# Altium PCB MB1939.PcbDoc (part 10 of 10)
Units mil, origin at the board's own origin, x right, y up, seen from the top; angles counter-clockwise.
Board outline 5910.64 x 4335.93 mil, 6 copper layers (Top Layer, l2_GND, L3_SIG, L4_VCC, L5_GND, Bottom Layer), stack 58.424 mil thick; 635 components, 489 nets, 2289 pads, 1388 vias.
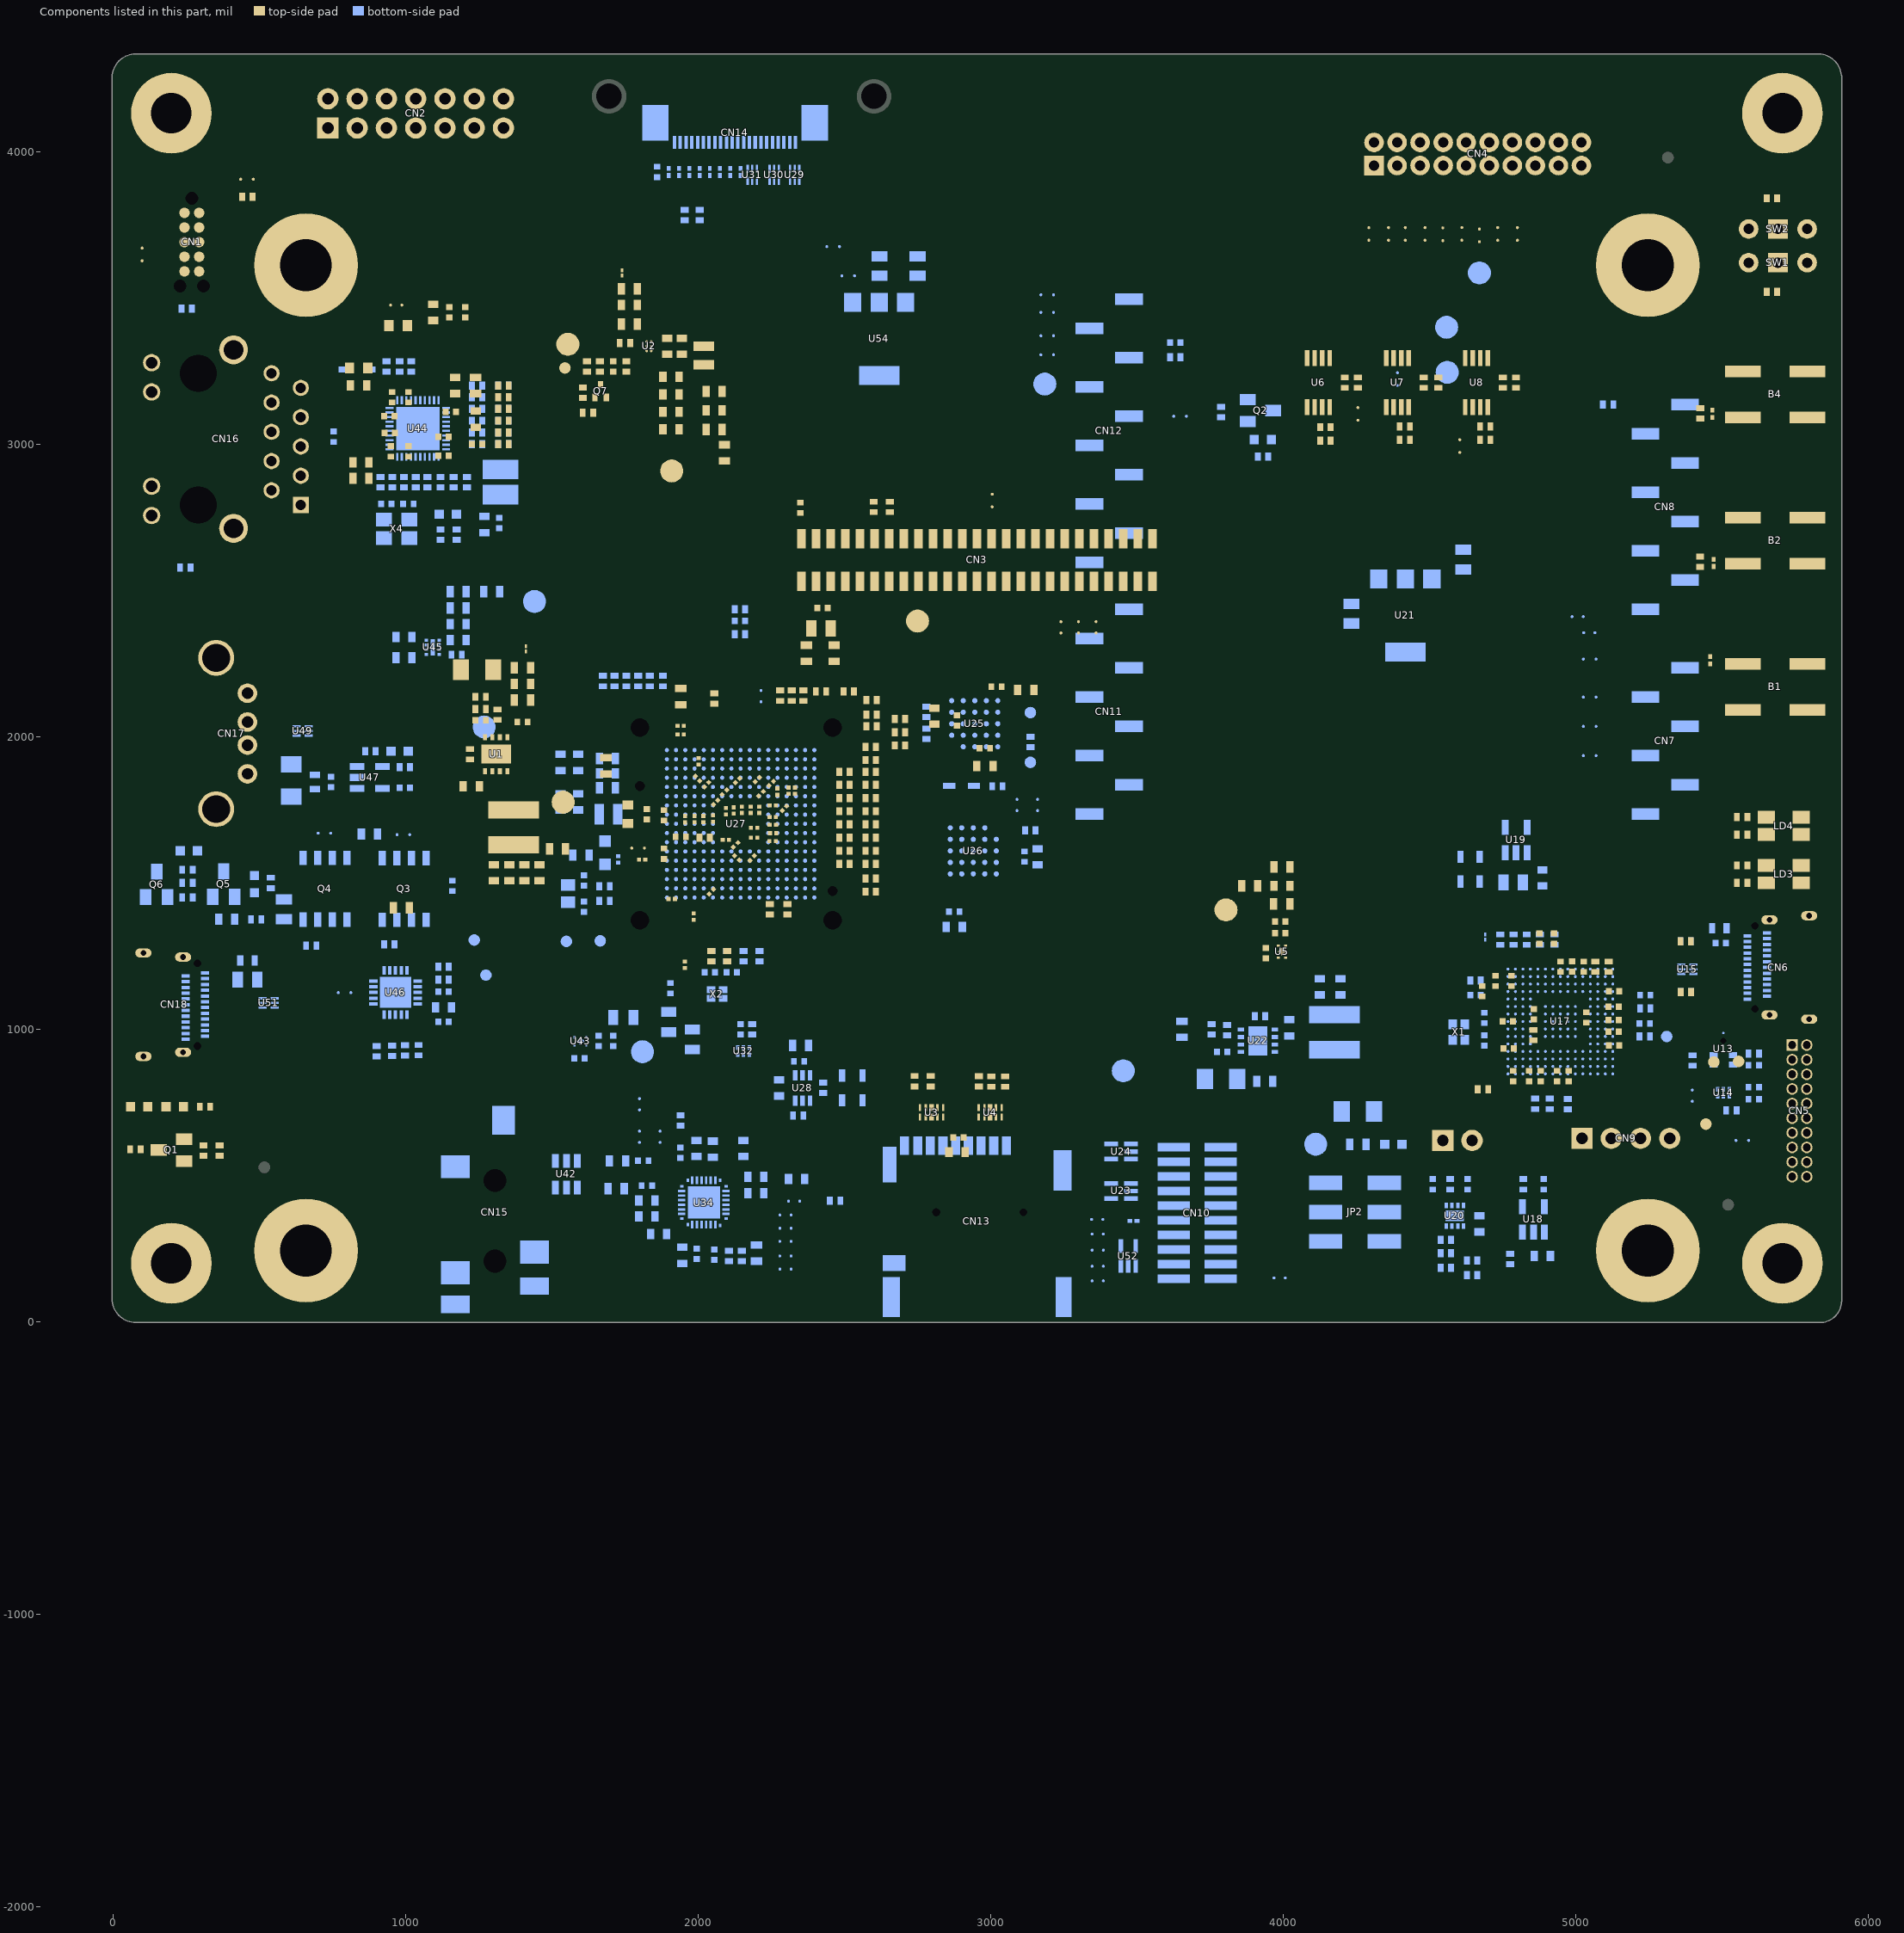
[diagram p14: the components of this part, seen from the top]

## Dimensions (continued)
-0.1,79.04 to 5905.33,71.52 on M2-Board Dimensions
